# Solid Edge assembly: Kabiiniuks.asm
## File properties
Author: Mac
Template: Normal.asm
Last saved by: Mac
Revision: 2
Application: Solid Edge
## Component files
ukseraam.par
uks.par
rull.par
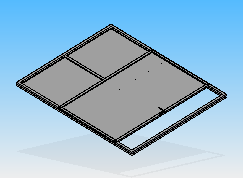
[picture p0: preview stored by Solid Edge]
